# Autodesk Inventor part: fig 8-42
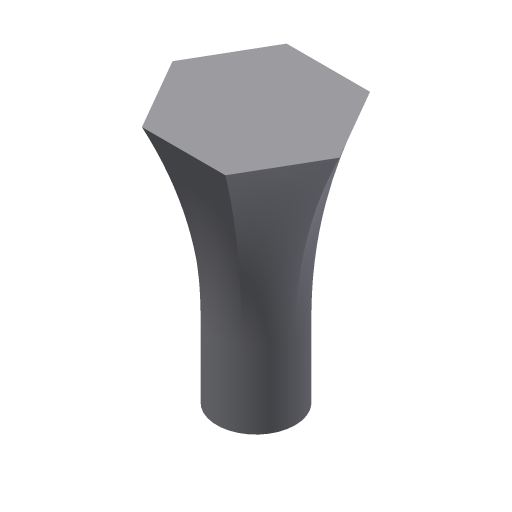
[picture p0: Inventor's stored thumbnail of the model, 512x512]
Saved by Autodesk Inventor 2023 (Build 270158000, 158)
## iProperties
Created: 2004-05
Part Number: fig 8-42
Document SubType Name: Modeling
Designer: CADCIM Technologies
Manufacturer: Standard
Standards Organization: Custom
Density: 1 g/cm^3
Material: Generic
Appearance: Default
Author: CADCIM Technologies
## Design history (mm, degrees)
sketch "Sketch1"
  geometry: C1 r 16.344 at (0, 0)
  constraints: 1 centre point
extrude "Extrusion1" new body sketch "Sketch1" distance "d0" = 30.75; taper "d1" = 0 deg
workplane "Work Plane1"
sketch "Sketch2"
  geometry: L1 (34.788, 0)-(17.394, -30.128); L2 (17.394, -30.128)-(-17.394, -30.128); L3 (-17.394, -30.128)-(-34.788, 0); L4 (-34.788, 0)-(-17.394, 30.128); L5 (-17.394, 30.128)-(17.394, 30.128); L6 (17.394, 30.128)-(34.788, 0); 2 further points
  constraints: 12 end point, 1 coincident, 12 other
loft "Loft2" sketch "Sketch2" dims "d8" = 90 deg, "d11" = 10, "d12" = 0, "d13" = 90 deg
  node "Edges2"
body "Solid1"
other parameters: "d2" = 75
